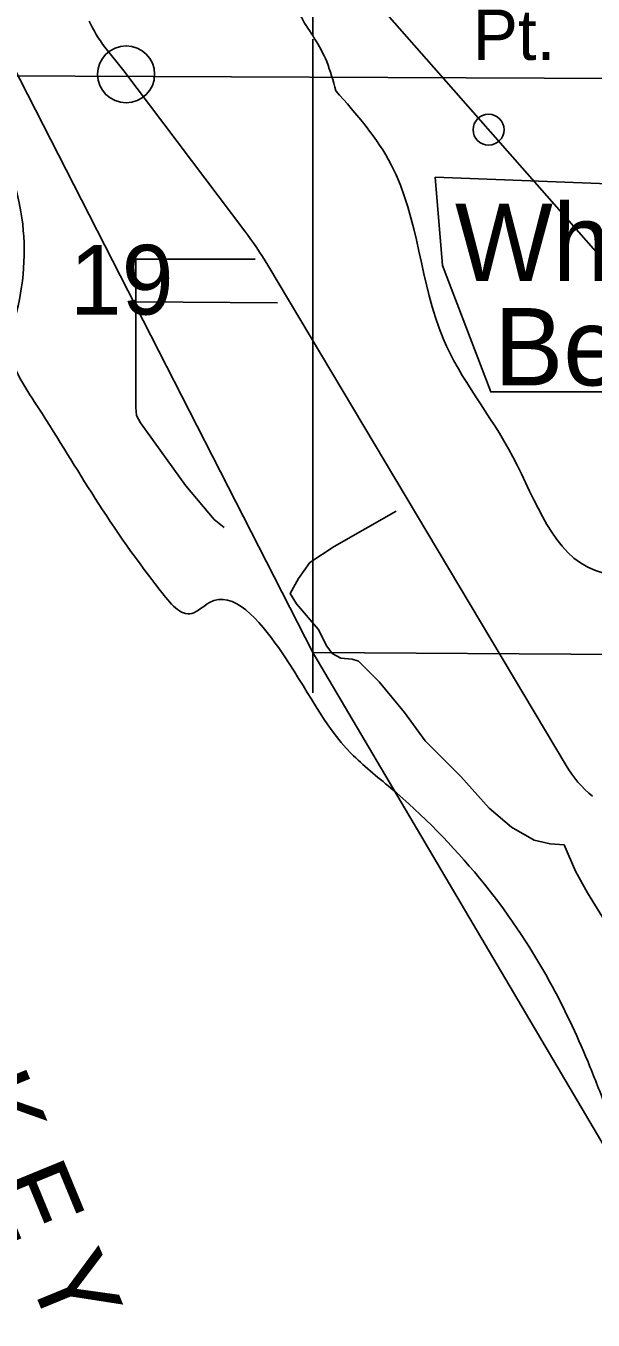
# Model space of a CAD drawing. Extents: x 408847 to 817539, y 923858 to 1151780.
# Drawn here: x 481921 to 485580, y 1052511 to 1060869 of the extents above; entities that cross this region are included whole.
import ezdxf

# ---------------------------------------------------------------- set-up
doc = ezdxf.new("R2010")
doc.units = 0
for name, color, linetype in [('County Route Divided Highway Outline and Fill', 7, 'Continuous'), ('Geographic Features Text', 7, 'Continuous'), ('Islands Coastal Text (Keys etc)', 7, 'Continuous'), ('Lakes and Ponds', 7, 'Continuous'), ('Level 12', 7, 'Continuous'), ('Level 39', 7, 'Continuous'), ('Level 43', 7, 'Continuous'), ('Local Roads Paved', 7, 'Continuous'), ('Narrow River Creek and Branch and Slough', 7, 'Continuous'), ('Quad Borders', 7, 'Continuous'), ('Section Lines', 7, 'Continuous'), ('Town Centers', 7, 'Continuous')]:
    doc.layers.add(name, color=color, linetype=linetype)

msp = doc.modelspace()

# ---------------------------------------------------------------- linework, layer by layer
at = {"layer": 'County Route Divided Highway Outline and Fill'}
for p, q in [((482431.1, 1060731.7), (482552, 1060577.9)), ((482552, 1060577.9), (483333.8, 1059543.1)), ((483481.1, 1059324), (485405.4, 1056091.7))]:
    msp.add_line(p, q, dxfattribs=at)
for centre, radius, start, end in [((483060, 1061226.1), 800, 204.06481, 218.16485), ((481418.9, 1058096.3), 2400, 30.76666, 37.07216), ((486049.9, 1056475.3), 750, 210.76675, 230.87056)]:
    msp.add_arc(centre, radius, start, end, dxfattribs=at)
at = {"layer": 'Lakes and Ponds'}
for points in [[(483919.4, 1060449.7), (483861.4, 1060637.5), (483781.3, 1060789.7), (483669.2, 1061051.9), (483701.3, 1061172.1), (483655.2, 1061326.2), (483505, 1061370.3), (483388.9, 1061560.5), (483281.4, 1061766.3)], [(486531.6, 1060527.4), (486357.4, 1060703.6), (486217.2, 1060807.7), (486163.2, 1060859.8), (485991, 1061013.9), (485067.3, 1061769.9)], [(481538.1, 1060563.4), (481889.3, 1059667.7), (481860.9, 1059020.1), (481818.8, 1058798.4), (481974.8, 1058443.9), (482787.1, 1057222.8), (482991.3, 1057073.9), (483105.5, 1057145.4), (483551.8, 1056851.5), (484020, 1056169.7), (484274.2, 1055946.7), (485298.8, 1054698.6), (485545, 1054182.5), (485656.3, 1053901.2)], [(486615.6, 1055310.8), (486198.3, 1055858.1), (486050.4, 1056522.4), (485966.4, 1056628.8), (485906.5, 1057024.8), (486259, 1057237.2), (486867.7, 1057454.3), (486869.8, 1057580.3), (486629.6, 1057721.3), (485950.7, 1057356.5), (485594.3, 1057352.1), (485062, 1058086.2), (484611.9, 1058849.8), (484278.3, 1059971.2), (483919.4, 1060449.7)]]:
    msp.add_spline(points, degree=3, dxfattribs=at)
at = {"layer": 'Level 12'}
msp.add_lwpolyline([(484560.5, 1059891.6), (487071.7, 1059793.7), (487789.2, 1058700.4), (487707.7, 1058553.6), (487088, 1058504.6), (484919.2, 1058504.6), (484609.4, 1059320.5)], close=True, dxfattribs=at)
msp.add_circle((484905.6, 1060198), 99.8, dxfattribs=at)
at = {"layer": 'Local Roads Paved'}
msp.add_line((483545.1, 1059080.3), (482631, 1059086.4), dxfattribs=at)
for points in [[(483399.8, 1059361.9), (482631, 1059361.9), (482631, 1058402)], [(482631, 1058405), (482634, 1058353.6), (482661.2, 1058305.1), (482951.8, 1057899.3), (483136.5, 1057681.3), (483200, 1057629.8)], [(484309.4, 1057735.8), (483909.8, 1057505.7), (483752.4, 1057402.7), (483679.8, 1057299.8), (483625.3, 1057202.9), (483667.7, 1057136.2), (483806.9, 1056972.7), (483861.4, 1056863.7), (483897.7, 1056815.2), (483952.2, 1056785), (484024.9, 1056778.9), (484067.2, 1056766.8), (484200.4, 1056633.6), (484363.9, 1056433.7), (484497.1, 1056252), (484727.1, 1056021.9), (484908.7, 1055815.9), (485054, 1055694.8), (485199.3, 1055610), (485302.2, 1055585.8), (485393, 1055579.7), (485465.7, 1055410.2), (485544.4, 1055270.9), (485641.2, 1055113.4)]]:
    msp.add_lwpolyline(points, dxfattribs=at)
at = {"layer": 'Narrow River Creek and Branch and Slough'}
for points in [[(490280.6, 1051568), (487084.7, 1057720.6), (485581.5, 1059428.1), (483522.3, 1061773.5), (483007.5, 1062834.3), (482853, 1063133), (482087, 1064025.6), (481376.6, 1064839.5)], [(484625.2, 1060517.3), (484047.9, 1061174.9)], [(485763.5, 1059221.3), (485581.5, 1059428.1), (485186, 1059878.6)]]:
    msp.add_lwpolyline(points, dxfattribs=at)
at = {"layer": 'Quad Borders'}
for p in [(453162.9, 1060675.2), (453264.3, 1060674.7)]:
    msp.add_line(p, (493776.8, 1060493), dxfattribs=at)
at = {"layer": 'Section Lines'}
for p, q in [((481243.8, 1061772.1), (483771.9, 1056822.8)), ((483771.6, 1061784.4), (483771.7, 1060802.2)), ((483771.7, 1060782.3), (483771.9, 1056561.4)), ((485871.3, 1056808.6), (483771.9, 1056822.8))]:
    msp.add_line(p, q, dxfattribs=at)
msp.add_lwpolyline([(483771.9, 1056822.8), (487057.9, 1051250)], dxfattribs=at)
at = {"layer": 'Town Centers'}
msp.add_circle((482567.7, 1060555.7), 184, dxfattribs=at)

# ---------------------------------------------------------------- texts
at = {"layer": 'Geographic Features Text'}
msp.add_text('Pt.', height=325, rotation=0.00053, dxfattribs=at).set_placement((484804.9, 1060648.8))
at = {"layer": 'Islands Coastal Text (Keys etc)'}
msp.add_text('K E Y', height=500, rotation=292.402, dxfattribs=at).set_placement((481440.9, 1053987.4))
at = {"layer": 'Level 39'}
for s, p in [('White', (484688.8, 1059220.3)), ('Beach', (484941.6, 1058546.6))]:
    msp.add_text(s, height=500, rotation=0.00052, dxfattribs=at).set_placement(p)
at = {"layer": 'Level 43'}
msp.add_text('19', height=450, rotation=0.00052, dxfattribs=at).set_placement((482204.6, 1059004.5))

doc.saveas('drawing.dxf')
